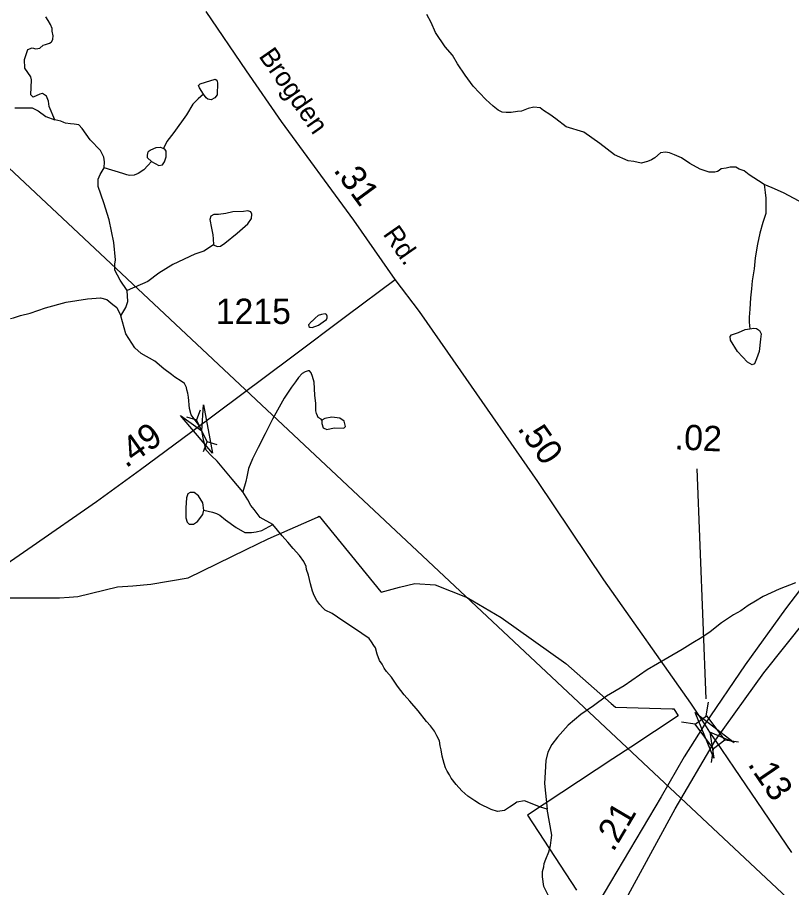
# Model space of a CAD drawing. Extents: x 2056842 to 2160602, y 826753 to 1016856.
# Drawn here: x 2083516 to 2087343, y 880850 to 885150 of the extents above; entities that cross this region are included whole.
import ezdxf

# ---------------------------------------------------------------- set-up
doc = ezdxf.new("R2010")
doc.units = 0
for name, color, linetype in [('Exist Boundary Political City Limit New', 7, 'Continuous'), ('Exist Hydrographic Creek Single Shore', 7, 'Continuous'), ('Exist Hydrographic Misc Water Feature', 7, 'Continuous'), ('Exist Road Primary Interstate Divided Center Attributed', 7, 'Continuous'), ('Exist Road Primary Interstate Mileage Hundredths English Label', 7, 'Continuous'), ('Exist Road Secondary Mileage Hundredths English Label', 7, 'Continuous'), ('Exist Road Secondary Structure Pipe Attributed CELL', 7, 'Continuous'), ('Exist Road Secondary Structure Pipe CELL', 7, 'Continuous'), ('Exist Road Secondary Structure Standard Bridge Attributed CELL', 7, 'Continuous'), ('Exist Road Secondary Structure Standard Bridge CELL', 7, 'Continuous'), ('Exist Road Secondary Type 51 Attributed', 7, 'Continuous'), ('Exist Road Secondary Type 51 Label', 7, 'Continuous'), ('Exist Road Secondary Type 51 Number Label', 7, 'Continuous'), ('Exist Utilities Electrical Transmission Line', 7, 'Continuous'), ('Map Preparation Boundary City Limit Buffer Line', 7, 'Continuous')]:
    doc.layers.add(name, color=color, linetype=linetype)

msp = doc.modelspace()

# ---------------------------------------------------------------- linework, layer by layer
at = {"layer": 'Exist Boundary Political City Limit New'}
msp.add_lwpolyline([(2083268.6, 882281.4), (2083724.4, 882281.1), (2083772.2, 882284.9), (2083815.5, 882288.2), (2084010.8, 882335.4), (2084087.5, 882341.6), (2084175.8, 882348.7), (2084360.2, 882380.9), (2084647.6, 882520.5), (2084756.4, 882573.4), (2085000, 882680.6), (2085008.5, 882684.4), (2085312.6, 882311.4), (2085314.8, 882308.8), (2085405.4, 882334.6), (2085481.2, 882352.8), (2085580.5, 882346.2), (2085739.6, 882283.8), (2085908, 882184.9), (2086227.4, 881957.2), (2086451.4, 881759.6), (2086472, 881741.4), (2086753, 881732.8), (2086761.1, 881732.6), (2086781.5, 881698.1), (2086548.5, 881544.3), (2086459.6, 881485.6), (2086037.9, 881207.4), (2086279.1, 880836.7)], dxfattribs=at)
at = {"layer": 'Exist Hydrographic Creek Single Shore'}
for points in [[(2083701, 884644.1), (2083673.5, 884709.1), (2083669.8, 884736.6), (2083659.8, 884760.7), (2083639.8, 884774.5), (2083627.3, 884770.7), (2083594.8, 884755.7), (2083583.6, 884767), (2083586.1, 884840.8), (2083582.3, 884855.8), (2083552.4, 884898.3), (2083551.1, 884942), (2083567.4, 884992), (2083588.6, 884999.5), (2083607.2, 884994.4), (2083627.3, 884998.3), (2083643.3, 885012.4), (2083655.2, 885016.4), (2083675.3, 885022.6), (2083683.3, 885026.7), (2083687.3, 885030.5), (2083691.2, 885042.6), (2083693.1, 885058.6), (2083689, 885082.6), (2083689, 885094.8), (2083680.8, 885114.6), (2083668.8, 885134.6), (2083656.7, 885152.5)], [(2087207.1, 884323.8), (2087178.9, 884341.8), (2087133, 884371.6), (2087108.8, 884391.5), (2087082.7, 884399.3), (2087066.8, 884409.4), (2087054.7, 884409.3), (2087038.6, 884409.4), (2087018.8, 884405.2), (2086994.8, 884401.1), (2086984.8, 884393.1), (2086976.8, 884389), (2086963, 884385), (2086934.7, 884384.9), (2086890.8, 884400.6), (2086838.9, 884428.6), (2086798.7, 884456.3), (2086764.6, 884470.5), (2086738.5, 884480.2), (2086718.6, 884484.2), (2086694.6, 884480.1), (2086666.5, 884456.1), (2086650.5, 884445.9), (2086630.7, 884437.8), (2086598.7, 884429.9), (2086562.8, 884437.6), (2086534.6, 884441.8), (2086466.7, 884471.4), (2086394.3, 884527.3), (2086316.4, 884583.1), (2086228.3, 884608.5), (2086178, 884648.6), (2086147.9, 884670.2), (2086115.9, 884690.3), (2086100, 884702.4), (2086067.9, 884706), (2086039.9, 884700), (2086008.1, 884685.9), (2085988.1, 884684), (2085955.8, 884679.8), (2085931.9, 884679.6), (2085911.9, 884681.7), (2085892.1, 884691.6), (2085867.9, 884711.5), (2085831.8, 884743.4), (2085769.5, 884809.3), (2085729.3, 884864.9), (2085691.1, 884920.8), (2085667.1, 884963), (2085631.2, 885004.8), (2085582.7, 885074.7), (2085560.8, 885124.4), (2085540.6, 885164.5)], [(2083503.6, 884702.9), (2083569.8, 884702.9), (2083589.8, 884702.9), (2083618.6, 884687.9), (2083656.1, 884660.4), (2083701, 884644.1)], [(2083945.9, 884406.1), (2083947, 884435.5), (2083942.9, 884459.5), (2083926.8, 884491.4), (2083876, 884544.1), (2083837.2, 884601.6), (2083819.7, 884619.1), (2083797.2, 884622.9), (2083778.3, 884623.1), (2083754.4, 884626.8), (2083746.3, 884631), (2083730.4, 884636.9), (2083701, 884644.1)], [(2084058.9, 883799.9), (2084024.6, 883852), (2083997.2, 883900.7), (2083997.2, 883930.7), (2084000.7, 883951.7), (2083992.2, 884037.5), (2083969.7, 884148.8), (2083943.4, 884233.8), (2083915.9, 884313.8), (2083915.9, 884351.1), (2083924.7, 884373.6), (2083945.9, 884406.1)], [(2088321.3, 884129.2), (2088277.4, 884117), (2088245.5, 884097), (2088217.7, 884085.1), (2088177.6, 884066.9), (2088149.8, 884052.7), (2088111.8, 884042.7), (2088083.6, 884042.6), (2087993.9, 884050.3), (2087921.8, 884058.1), (2087837.6, 884063.7), (2087745.5, 884097.5), (2087643.5, 884131.1), (2087543.3, 884174.8), (2087459.2, 884200.5), (2087379.3, 884242.2), (2087303.1, 884282.2), (2087247.2, 884307.9), (2087207.1, 884323.8)], [(2084027.1, 883674.6), (2084052.1, 883716.8), (2084062.1, 883745.6), (2084058.9, 883799.9)], [(2083481.7, 883662.4), (2083497.7, 883664.4), (2083531.6, 883676.3), (2083579.5, 883688.6), (2083655.2, 883714.8), (2083757.3, 883743.1), (2083863.3, 883759.5), (2083927.3, 883763.6), (2083959.1, 883755.9), (2083987.4, 883731.7), (2084007.3, 883715.7), (2084027.1, 883674.6)], [(2084630.6, 882805.2), (2084578.2, 882867.7), (2084544.4, 882907.7), (2084504.4, 882956.5), (2084475.7, 882984), (2084449.4, 883012), (2084437.3, 883055.1), (2084427.9, 883106.3), (2084409.1, 883139.1), (2084375.8, 883186.3), (2084367, 883217.5), (2084362.6, 883272.9), (2084358.5, 883293), (2084354.5, 883308.9), (2084352.5, 883321), (2084342.4, 883340.9), (2084326.2, 883352.8), (2084294.2, 883372.8), (2084278.3, 883384.6), (2084240.2, 883412.6), (2084196, 883450.3), (2084128.4, 883489.6), (2084097.1, 883517.1), (2084052.1, 883585.8), (2084027.1, 883674.6)], [(2084778.5, 882644.2), (2084716.9, 882678.9), (2084686.9, 882717.7), (2084670.6, 882737.7), (2084654.4, 882766.4), (2084630.6, 882805.2)], [(2086135, 881237.3), (2086101.3, 881247.3), (2086022.6, 881278.7), (2085985.1, 881271.2), (2085971.3, 881262.5), (2085947.6, 881247.5), (2085923.9, 881231.2), (2085888.9, 881226.2), (2085857.6, 881235), (2085800.5, 881263.7), (2085776.6, 881277.6), (2085742.6, 881301.6), (2085712.6, 881327.5), (2085684.4, 881359.3), (2085660.5, 881391.2), (2085652.3, 881407.2), (2085640.2, 881425.1), (2085632.3, 881441), (2085626.2, 881463.2), (2085616.1, 881499.1), (2085609.9, 881531.1), (2085605.7, 881550.9), (2085601.9, 881574.9), (2085589.6, 881599.1), (2085577.6, 881623), (2085557.5, 881649), (2085537.6, 881670.7), (2085497.3, 881722.7), (2085455, 881770.5), (2085427.1, 881802.3), (2085394.9, 881844.3), (2085364.6, 881890.2), (2085340.6, 881918.3), (2085328.8, 881934.2), (2085318.7, 881954.1), (2085306.6, 881972.1), (2085294.5, 882003.9), (2085286.2, 882033.9), (2085278.3, 882045.9), (2085266.2, 882063.8), (2085254.1, 882079.8), (2085218.2, 882105.8), (2085168, 882139.7), (2085124, 882167.5), (2085071.9, 882203.4), (2085037.8, 882221.1), (2085023.6, 882233.2), (2085011.8, 882248.9), (2084995.8, 882268.9), (2084983.5, 882293.1), (2084975.4, 882314.9), (2084965.3, 882350.9), (2084955.4, 882392.8), (2084945.1, 882420.9), (2084943.2, 882436.7), (2084931.2, 882460.9), (2084910.8, 882490.8), (2084879, 882524.6), (2084852.8, 882556.7), (2084824.6, 882588.4), (2084778.5, 882644.2)], [(2087361.3, 882356.3), (2087281.3, 882324.2), (2087201.4, 882288.1), (2087163.6, 882265.8), (2087127.8, 882244.1), (2087091.9, 882217.8), (2087055.8, 882197.7), (2086995.9, 882157.3), (2086940.1, 882113.5), (2086898.1, 882085.4), (2086854.2, 882059.1), (2086802.5, 882026.7), (2086730.6, 881984.5), (2086628.7, 881926.5), (2086514.9, 881846), (2086427.1, 881795.6), (2086363.3, 881747.6), (2086301.6, 881705.4), (2086237.6, 881653), (2086186, 881593.1), (2086157.9, 881556.8), (2086138.4, 881518.8), (2086128.3, 881476.9), (2086124, 881420.7), (2086120.7, 881364.8), (2086135, 881237.3)], [(2086644.8, 880288.2), (2086576.1, 880340.7), (2086534.8, 880397), (2086509.9, 880422), (2086426.9, 880515.7), (2086412.8, 880531.8), (2086402.8, 880543.5), (2086248.7, 880668.4), (2086203.7, 880712.1), (2086165, 880766.8), (2086138.8, 880813), (2086118.8, 880855), (2086111.7, 880902.5), (2086111.6, 880928.8), (2086117.6, 880952.6), (2086119.6, 880968.7), (2086127.6, 880990.8), (2086143.4, 881026.9), (2086151.3, 881056.9), (2086155.1, 881084.7), (2086157.3, 881108.6), (2086135, 881237.3)]]:
    msp.add_lwpolyline(points, dxfattribs=at)
at = {"layer": 'Exist Hydrographic Misc Water Feature'}
for points in [[(2084435.8, 884771.1), (2084415.7, 884801.6), (2084412, 884814.1), (2084419.5, 884821.6), (2084445.7, 884830.4), (2084494.5, 884844.1), (2084501.9, 884840.4), (2084505.7, 884826.6), (2084503.2, 884767.9), (2084492, 884752.9), (2084474.5, 884742.9), (2084458.2, 884745.4), (2084449.5, 884752.9), (2084435.8, 884771.1)], [(2084435.8, 884771.1), (2084410.2, 884747), (2084384.2, 884721), (2084352.6, 884668.9), (2084289, 884580.8), (2084254.8, 884536.5), (2084239, 884502.4)], [(2084179.1, 884438.4), (2084159, 884456.5), (2084159, 884464.2), (2084159, 884468.3), (2084162.7, 884486.3), (2084167, 884490.5), (2084173.2, 884494.5), (2084191, 884502.3), (2084202.7, 884506.2), (2084223, 884508.5), (2084239, 884502.4)], [(2084179.1, 884438.4), (2084215.8, 884417.8), (2084233.3, 884421.6), (2084242.9, 884436.5), (2084251.1, 884460.8), (2084251.1, 884472.6), (2084251.1, 884480.7), (2084250.8, 884489.1), (2084244.7, 884498.6), (2084239, 884502.4)], [(2084179.1, 884438.4), (2084161.3, 884418.3), (2084141.4, 884396.2), (2084113.3, 884378.2), (2084093.4, 884370.3), (2084069.6, 884368.2), (2084057.5, 884372), (2084037.2, 884377.9), (2083945.9, 884406.1)], [(2087207.1, 884323.8), (2087211.6, 884283.8), (2087215.5, 884256), (2087215.3, 884211.9), (2087215.5, 884180.2), (2087199.7, 884135.9), (2087186, 884084), (2087173.9, 884029.8), (2087162.6, 883961.7), (2087156.7, 883907.9), (2087148.3, 883847.9), (2087144.6, 883807.8), (2087139, 883763.6), (2087136.8, 883707.5), (2087133.3, 883668), (2087133.5, 883643.6), (2087136.7, 883610.8)], [(2084485.7, 884025.6), (2084504.4, 884017.5), (2084519.4, 884018.8), (2084541.9, 884033.8), (2084603.2, 884083.8), (2084655.6, 884130), (2084673.1, 884156.3), (2084675.6, 884177.5), (2084669.4, 884188.8), (2084655.6, 884193.8), (2084634.4, 884190), (2084581.9, 884188.8), (2084545.7, 884181.3), (2084510.7, 884176.3), (2084487, 884176.3), (2084472, 884167.5), (2084467, 884151.3), (2084475.7, 884108.8), (2084482, 884075), (2084483.2, 884056.3), (2084485.7, 884025.6)], [(2084485.7, 884025.6), (2084438.2, 883994.4), (2084393.2, 883979.4), (2084284.5, 883929.4), (2084214.6, 883885.6), (2084160.8, 883844.4), (2084059.2, 883800)], [(2085037.3, 883685), (2085019.2, 883681.3), (2085003.2, 883677.2), (2084987.2, 883662.9), (2084973.5, 883648.8), (2084969.8, 883646.9), (2084955.6, 883630.8), (2084957.3, 883622.8), (2084961.8, 883618.9), (2084973.7, 883616.7), (2085003.8, 883629.2), (2085027.6, 883645.1), (2085043.4, 883657.3), (2085047.5, 883665.2), (2085047.7, 883673.3), (2085043.4, 883681.2), (2085037.3, 883685)], [(2087136.7, 883610.8), (2087155.9, 883614.3), (2087169.6, 883613.1), (2087183.4, 883603.1), (2087192.1, 883586.8), (2087189.6, 883560.6), (2087182.1, 883499.3), (2087169.6, 883461.8), (2087158.4, 883438.1), (2087147.1, 883433.1), (2087124.6, 883445.6), (2087075.9, 883498.1), (2087040.9, 883554.3), (2087038.4, 883573.1), (2087044.7, 883580.6), (2087079.7, 883593.1), (2087113.4, 883606.8), (2087136.7, 883610.8)], [(2085021.7, 883160), (2085017, 883165.1), (2085003, 883173.3), (2084998.9, 883181.2), (2084994.8, 883193.2), (2084990.9, 883205), (2084990.9, 883241.2), (2084987, 883283.2), (2084982.7, 883347.2), (2084974.3, 883375.2), (2084968.4, 883393.2), (2084960.2, 883402.9), (2084952.6, 883402.8), (2084938.2, 883398.9), (2084924.1, 883390.9), (2084906.4, 883370.9), (2084890.4, 883349), (2084870.7, 883322.7), (2084834.5, 883268.6), (2084777.2, 883164.4), (2084741.4, 883092.4), (2084705.5, 883024.4), (2084677.8, 882968.1), (2084657.9, 882920), (2084649.9, 882880.2), (2084646, 882856.1), (2084630.6, 882805.2)], [(2085021.7, 883160), (2085020.5, 883142.5), (2085028, 883121.2), (2085045.5, 883113.7), (2085081.7, 883121.2), (2085130.4, 883120), (2085137.9, 883128.8), (2085131.7, 883155), (2085110.4, 883170), (2085070.5, 883175), (2085035.5, 883167.5), (2085021.7, 883160)], [(2084438.2, 882715.2), (2084432, 882751.4), (2084412, 882785.2), (2084389.5, 882801.5), (2084370.8, 882802.7), (2084358.3, 882795.2), (2084352, 882775.2), (2084349.5, 882726.4), (2084349.5, 882677.7), (2084355.8, 882655.2), (2084364.5, 882646.4), (2084387, 882645.2), (2084405.7, 882658.9), (2084433.2, 882692.7), (2084438.2, 882715.2)], [(2084438.2, 882715.2), (2084481.3, 882705.1), (2084500.6, 882697.5), (2084516.8, 882689.9), (2084544.5, 882667.7), (2084596.8, 882629.8), (2084640.9, 882604), (2084672.9, 882604), (2084696.9, 882608.1), (2084724.8, 882614.5), (2084778.7, 882644.4)]]:
    msp.add_lwpolyline(points, dxfattribs=at)
at = {"layer": 'Exist Road Primary Interstate Divided Center Attributed'}
for points in [[(2087578.1, 882575.2), (2087312.7, 882227.8), (2087112.9, 881950.5), (2086913.8, 881656.6)], [(2086966.9, 881577.7), (2087204.7, 881910.9), (2087614.1, 882424)], [(2086913.8, 881656.6), (2086812.4, 881495.1), (2086697.2, 881298.8), (2086416.5, 880823.6), (2086104.3, 880294.3), (2085757.9, 879705.6), (2085389, 879075.5), (2085071.4, 878540.8), (2084756.5, 877997.1), (2084428.1, 877431.8), (2084115.8, 876911.6), (2083719, 876326.5), (2083315.1, 875763), (2082934.5, 875231.9), (2082589.9, 874745.8), (2082168.8, 874149.9), (2082016.5, 873938.4)], [(2082028.6, 873734.2), (2082362.2, 874180.5), (2082750, 874681), (2083148.6, 875195.9), (2083527.4, 875694.6), (2083900.8, 876187.9), (2084261.6, 876715.3), (2084561.2, 877205), (2084920.2, 877849.5), (2085220.7, 878395), (2085715.6, 879311.3), (2085981, 879788.4), (2086215.9, 880224.1), (2086495.7, 880739), (2086767.4, 881239.4), (2086966.9, 881577.7)]]:
    msp.add_lwpolyline(points, dxfattribs=at)
at = {"layer": 'Exist Road Secondary Mileage Hundredths English Label'}
msp.add_line((2086920.4, 881781.9), (2086875.6, 882918.9), dxfattribs=at)
at = {"layer": 'Exist Road Secondary Structure Pipe Attributed CELL'}
msp.add_lwpolyline([(2084436.4, 883236), (2084480, 882996.1), (2084322.3, 883182.1), (2084427.9, 883106.3)], close=True, dxfattribs=at)
at = {"layer": 'Exist Road Secondary Structure Pipe CELL'}
for p, q in [((2084352.9, 883175.8), (2084401.3, 883160.6)), ((2084419.1, 883208.2), (2084401.3, 883160.6)), ((2084454.4, 883052), (2084401.3, 883160.6)), ((2084436.6, 883004.4), (2084454.4, 883052)), ((2084502.9, 883036.8), (2084454.4, 883052))]:
    msp.add_line(p, q, dxfattribs=at)
at = {"layer": 'Exist Road Secondary Structure Standard Bridge Attributed CELL'}
msp.add_lwpolyline([(2086957.7, 881489.5), (2086865.3, 881715.2), (2087058.1, 881565.9), (2086939.1, 881618.2)], close=True, dxfattribs=at)
at = {"layer": 'Exist Road Secondary Structure Standard Bridge CELL'}
for p, q in [((2086921.1, 881697.9), (2086931.1, 881766.2)), ((2086865.8, 881656.7), (2086797.6, 881666.7)), ((2087080.7, 881567.6), (2087012.5, 881577.5)), ((2086945.9, 881467.1), (2086955.9, 881535.3))]:
    msp.add_line(p, q, dxfattribs=at)
msp.add_lwpolyline([(2086955.9, 881535.3), (2086865.6, 881656.5), (2086922.2, 881698.7), (2087012.5, 881577.5)], close=True, dxfattribs=at)
at = {"layer": 'Exist Road Secondary Type 51 Attributed'}
for points in [[(2085383.6, 883855), (2085179.3, 884147.9), (2084821, 884634.6), (2084648.2, 884885), (2084449.6, 885178.4)], [(2083282.3, 882325.7), (2083590.2, 882537.6), (2083908.1, 882756.9), (2084124.4, 882915.2), (2084371.4, 883099.2), (2084872.1, 883473.2), (2085145.2, 883677), (2085383.6, 883855)], [(2086913.8, 881656.6), (2086843.9, 881760.4), (2086414.1, 882370.9), (2086088.3, 882856.6), (2085707.3, 883403.1), (2085503.7, 883697.3), (2085383.6, 883855)], [(2086966.9, 881577.7), (2086939.1, 881618.2), (2086913.8, 881656.6)], [(2087343.7, 881023.3), (2087059.9, 881439.9), (2086966.9, 881577.7)]]:
    msp.add_lwpolyline(points, dxfattribs=at)
at = {"layer": 'Exist Utilities Electrical Transmission Line'}
msp.add_lwpolyline([(2090208.9, 878090.6), (2086715.1, 881367.1), (2080736.5, 886973.8)], dxfattribs=at)
at = {"layer": 'Map Preparation Boundary City Limit Buffer Line'}
msp.add_lwpolyline([(2083268.6, 882281.4), (2083724.4, 882281.1), (2083772.2, 882284.9), (2083815.5, 882288.2), (2084010.8, 882335.4), (2084087.5, 882341.6), (2084175.8, 882348.7), (2084360.2, 882380.9), (2084647.6, 882520.5), (2084756.4, 882573.4), (2085000, 882680.6), (2085008.5, 882684.4), (2085312.6, 882311.4), (2085314.8, 882308.8), (2085405.4, 882334.6), (2085481.2, 882352.8), (2085580.5, 882346.2), (2085739.6, 882283.8), (2085908, 882184.9), (2086227.4, 881957.2), (2086451.4, 881759.6), (2086472, 881741.4), (2086753, 881732.8), (2086761.1, 881732.6), (2086781.5, 881698.1), (2086548.5, 881544.3), (2086459.6, 881485.6), (2086037.9, 881207.4), (2086279.1, 880836.7)], dxfattribs=at)

# ---------------------------------------------------------------- texts
at = {"layer": 'Exist Road Primary Interstate Mileage Hundredths English Label'}
msp.add_text('.21', height=125, rotation=59.4315, dxfattribs=at).set_placement((2086461.1, 881022))
at = {"layer": 'Exist Road Secondary Mileage Hundredths English Label'}
for s, rotation, p in [('.31', 306.357, (2085075.1, 884394.9)), ('.49', 35.4532, (2084052.9, 882920)), ('.50', 305.1733, (2085984.6, 883118.1)), ('.02', 357.1825, (2086762.6, 883015.7)), ('.13', 304.2593, (2087122.4, 881459.2))]:
    msp.add_text(s, height=125, rotation=rotation, dxfattribs=at).set_placement(p)
at = {"layer": 'Exist Road Secondary Type 51 Label'}
for s, p in [('Brogden', (2084706.2, 884958.1)), ('Rd.', (2085320.2, 884078.9))]:
    msp.add_text(s, height=95, rotation=304.9276, dxfattribs=at).set_placement(p)
at = {"layer": 'Exist Road Secondary Type 51 Number Label'}
msp.add_text('1215', height=125, dxfattribs=at).set_placement((2084496.3, 883635))

doc.saveas('drawing.dxf')
